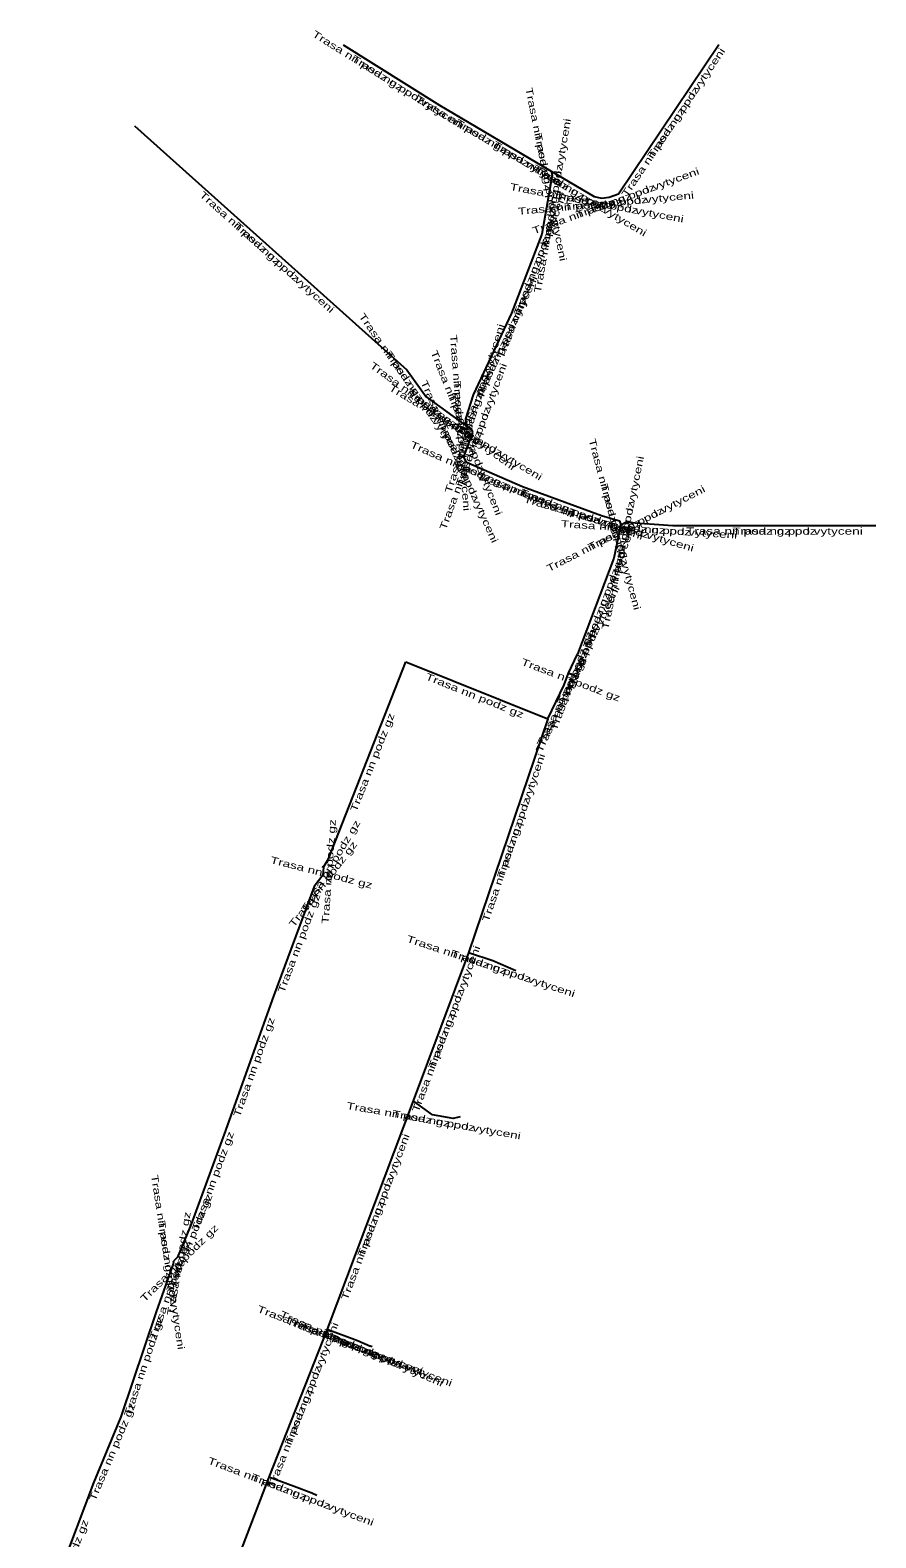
# Model space of a CAD drawing. Extents: x -644332 to -644190, y -1042435 to -1042173.
# Drawn here: x -644249.9 to -644189.5, y -1042280.3 to -1042172.8 of the extents above; entities that cross this region are included whole.
import ezdxf
from ezdxf.enums import TextEntityAlignment as Align

# ---------------------------------------------------------------- set-up
doc = ezdxf.new("R2010")
doc.units = 0
doc.header["$LTSCALE"] = 0.2
doc.layers.add('11', color=7, linetype='Continuous', lineweight=25)
doc.layers.add('33', color=7, linetype='Continuous')

msp = doc.modelspace()

# ---------------------------------------------------------------- linework, layer by layer
at = {"layer": '11'}
for p, q in [((-644227.53, -1042173.85), (-644220.65, -1042178.14)), ((-644227.53, -1042173.85), (-644220.65, -1042178.14)), ((-644207.88, -1042184.48), (-644200.71, -1042173.82)), ((-644207.88, -1042184.48), (-644200.71, -1042173.82)), ((-644220.65, -1042178.14), (-644212.68, -1042182.85)), ((-644220.65, -1042178.14), (-644212.68, -1042182.85)), ((-644242.42, -1042179.63), (-644222.97, -1042197.02)), ((-644242.42, -1042179.63), (-644222.97, -1042197.02)), ((-644212.62, -1042183.15), (-644213.35, -1042187.35)), ((-644212.62, -1042183.15), (-644213.35, -1042187.35)), ((-644212.68, -1042182.85), (-644209.61, -1042184.67)), ((-644212.68, -1042182.85), (-644212.62, -1042183.15)), ((-644212.68, -1042182.85), (-644212.62, -1042183.15)), ((-644212.68, -1042182.85), (-644209.61, -1042184.67)), ((-644208.54, -1042184.72), (-644207.88, -1042184.48)), ((-644208.54, -1042184.72), (-644207.88, -1042184.48)), ((-644209.61, -1042184.67), (-644209.08, -1042184.77)), ((-644209.61, -1042184.67), (-644209.08, -1042184.77)), ((-644209.08, -1042184.77), (-644208.54, -1042184.72)), ((-644209.08, -1042184.77), (-644208.54, -1042184.72)), ((-644213.35, -1042187.35), (-644215.52, -1042192.98)), ((-644213.35, -1042187.35), (-644215.52, -1042192.98)), ((-644215.52, -1042192.98), (-644218.25, -1042198.81)), ((-644215.52, -1042192.98), (-644218.25, -1042198.81)), ((-644222.97, -1042197.02), (-644221.61, -1042198.96)), ((-644222.97, -1042197.02), (-644221.61, -1042198.96)), ((-644221.61, -1042198.96), (-644218.75, -1042201.03)), ((-644218.25, -1042198.81), (-644218.79, -1042200.51)), ((-644218.25, -1042198.81), (-644218.79, -1042200.51)), ((-644218.79, -1042200.51), (-644218.75, -1042201.03)), ((-644218.79, -1042200.51), (-644218.75, -1042201.03)), ((-644218.3, -1042201.49), (-644218.94, -1042203.22)), ((-644218.3, -1042201.49), (-644218.94, -1042203.22)), ((-644218.75, -1042201.03), (-644218.4, -1042201.24)), ((-644218.4, -1042201.24), (-644218.3, -1042201.49)), ((-644218.4, -1042201.24), (-644218.3, -1042201.49)), ((-644218.94, -1042203.22), (-644218.78, -1042203.58)), ((-644218.94, -1042203.22), (-644218.78, -1042203.58)), ((-644218.78, -1042203.58), (-644214.72, -1042205.35)), ((-644218.78, -1042203.58), (-644214.72, -1042205.35)), ((-644214.72, -1042205.35), (-644209.1, -1042207.41)), ((-644214.72, -1042205.35), (-644209.1, -1042207.41)), ((-644209.1, -1042207.41), (-644207.8, -1042207.79)), ((-644209.1, -1042207.41), (-644207.8, -1042207.79)), ((-644207.72, -1042208.09), (-644208.21, -1042210.46)), ((-644207.72, -1042208.09), (-644208.21, -1042210.46)), ((-644207.8, -1042207.79), (-644207.72, -1042208.09)), ((-644207.8, -1042207.79), (-644207.72, -1042208.09)), ((-644207.72, -1042208.09), (-644207.35, -1042207.9)), ((-644207.72, -1042208.09), (-644207.35, -1042207.9)), ((-644207.35, -1042207.9), (-644203.99, -1042208.12)), ((-644207.35, -1042207.9), (-644203.99, -1042208.12)), ((-644203.99, -1042208.12), (-644189.51, -1042208.13)), ((-644203.99, -1042208.12), (-644189.51, -1042208.13)), ((-644208.21, -1042210.46), (-644210.79, -1042217.31)), ((-644208.21, -1042210.46), (-644210.79, -1042217.31)), ((-644211.44, -1042218.65), (-644210.79, -1042217.31)), ((-644211.44, -1042218.65), (-644210.79, -1042217.31)), ((-644228.57, -1042231.9), (-644223.05, -1042217.85)), ((-644223.05, -1042217.85), (-644212.91, -1042221.92)), ((-644211.756, -1042219.496), (-644211.44, -1042218.65)), ((-644211.44, -1042218.65), (-644210.829, -1042218.88)), ((-644212.91, -1042221.92), (-644211.756, -1042219.496)), ((-644212.91, -1042221.92), (-644218.57, -1042238.61)), ((-644212.91, -1042221.92), (-644218.57, -1042238.61)), ((-644228.93, -1042232.5), (-644229.013, -1042232.479)), ((-644228.93, -1042232.5), (-644228.97, -1042233.06)), ((-644228.93, -1042232.5), (-644228.57, -1042231.9)), ((-644229.59, -1042233.87), (-644232.5, -1042241.69)), ((-644228.97, -1042233.06), (-644229.59, -1042233.87)), ((-644218.57, -1042238.61), (-644222.53, -1042249.17)), ((-644218.57, -1042238.61), (-644222.53, -1042249.17)), ((-644232.5, -1042241.69), (-644236.02, -1042251.55)), ((-644222.53, -1042249.17), (-644228.67, -1042265.44)), ((-644222.53, -1042249.17), (-644228.67, -1042265.44)), ((-644236.02, -1042251.55), (-644238.37, -1042257.95)), ((-644238.37, -1042257.95), (-644239.35, -1042260.31)), ((-644239.66, -1042260.79), (-644240.87, -1042264.21)), ((-644239.632, -1042260.62), (-644239.66, -1042260.79)), ((-644239.35, -1042260.31), (-644239.636, -1042260.594)), ((-644239.632, -1042260.62), (-644239.636, -1042260.594)), ((-644239.632, -1042260.62), (-644239.636, -1042260.594)), ((-644240.87, -1042264.21), (-644243.38, -1042271.7)), ((-644228.67, -1042265.44), (-644232.82, -1042276)), ((-644228.67, -1042265.44), (-644232.82, -1042276)), ((-644228.67, -1042265.44), (-644226.51, -1042266.27)), ((-644226.51, -1042266.27), (-644225.58, -1042266.67)), ((-644225.444, -1042266.722), (-644225.58, -1042266.67)), ((-644225.444, -1042266.722), (-644225.58, -1042266.67)), ((-644243.38, -1042271.7), (-644245.35, -1042276.4)), ((-644245.35, -1042276.4), (-644249.86, -1042288.43)), ((-644232.82, -1042276), (-644241.24, -1042297.96)), ((-644232.82, -1042276), (-644241.24, -1042297.96))]:
    msp.add_line(p, q, dxfattribs=at)
for points in [[(-644221.61, -1042198.96), (-644218.75, -1042201.03), (-644218.4, -1042201.24)], [(-644215.2, -1042239.9), (-644216.85, -1042239.18), (-644218.57, -1042238.61)], [(-644215.2, -1042239.9), (-644216.85, -1042239.18), (-644218.57, -1042238.61)], [(-644219.17, -1042250.31), (-644219.67, -1042250.42), (-644221.15, -1042250.16), (-644222.53, -1042249.17)], [(-644219.17, -1042250.31), (-644219.67, -1042250.42), (-644221.15, -1042250.16), (-644222.53, -1042249.17)], [(-644228.67, -1042265.44), (-644226.51, -1042266.27), (-644225.58, -1042266.67)], [(-644229.41, -1042277.31), (-644229.76, -1042277.14), (-644231.03, -1042276.68), (-644232.82, -1042276)], [(-644229.41, -1042277.31), (-644229.76, -1042277.14), (-644231.03, -1042276.68), (-644232.82, -1042276)]]:
    msp.add_lwpolyline(points, dxfattribs=at)

# ---------------------------------------------------------------- texts
at = {"layer": '33'}
for s, rotation, width, p in [('Trasa nn podz gz po vytyceni', 328.055, 1.45, (-644224.4348, -1042176.5458)), ('Trasa nn podz', 328.055, 1.4, (-644224.4348, -1042176.546)), ('Trasa nn podz gz po vytyceni', 56.075, 1.45, (-644203.7563, -1042179.5135)), ('Trasa nn podz gz po vytyceni', 281.31, 1.45, (-644213.287, -1042183.127)), ('Trasa nn podz', 56.075, 1.4, (-644203.7558, -1042179.513)), ('Trasa nn podz gz po vytyceni', 329.418, 1.45, (-644216.9967, -1042181.0537)), ('Trasa nn podz', 329.418, 1.4, (-644216.9967, -1042181.0541)), ('Trasa nn podz gz po vytyceni', 80.14, 1.45, (-644212.345, -1042185.3613)), ('Trasa nn podz', 281.31, 1.4, (-644213.2867, -1042183.1275)), ('Trasa nn podz gz po vytyceni', 329.339, 1.45, (-644211.4775, -1042184.3188)), ('Trasa nn podz gz po vytyceni', 19.983, 1.45, (-644207.9879, -1042185.2111)), ('Trasa nn podz', 329.339, 1.4, (-644211.477, -1042184.3188)), ('Trasa nn podz', 80.14, 1.4, (-644212.345, -1042185.3608)), ('Trasa nn podz gz po vytyceni', 318.201, 1.45, (-644233.1296, -1042188.808)), ('Trasa nn podz gz po vytyceni', 68.922, 1.45, (-644213.8288, -1042190.3989)), ('Trasa nn podz gz po vytyceni', 349.315, 1.45, (-644209.4659, -1042185.3588)), ('Trasa nn podz gz po vytyceni', 5.29, 1.45, (-644208.7505, -1042185.3921)), ('Trasa nn podz', 349.315, 1.4, (-644209.4649, -1042185.3586)), ('Trasa nn podz', 19.983, 1.4, (-644207.9884, -1042185.2115)), ('Trasa nn podz', 5.29, 1.4, (-644208.7495, -1042185.3918)), ('Trasa nn podz', 318.201, 1.4, (-644233.1296, -1042188.808)), ('Trasa nn podz', 68.922, 1.4, (-644213.8291, -1042190.3994)), ('Trasa nn podz gz po vytyceni', 64.908, 1.45, (-644216.2966, -1042196.1715)), ('Trasa nn podz gz po vytyceni', 305.032, 1.45, (-644222.8234, -1042198.363)), ('Trasa nn podz gz po vytyceni', 72.378, 1.45, (-644217.9005, -1042199.8572)), ('Trasa nn podz', 64.908, 1.4, (-644216.2964, -1042196.172)), ('Trasa nn podz gz po vytyceni', 274.399, 1.45, (-644219.4179, -1042200.8208)), ('Trasa nn podz', 305.032, 1.4, (-644222.8238, -1042198.3625)), ('Trasa nn podz gz po vytyceni', 291.801, 1.45, (-644218.9535, -1042201.6067)), ('Trasa nn podz gz po vytyceni', 324.104, 1.45, (-644220.5631, -1042200.5203)), ('Trasa nn podz gz po vytyceni', 69.698, 1.45, (-644218.0105, -1042202.5812)), ('Trasa nn podz', 72.378, 1.4, (-644217.9011, -1042199.8572)), ('Trasa nn podz gz po vytyceni', 329.036, 1.45, (-644218.9106, -1042201.692)), ('Trasa nn podz', 324.104, 1.4, (-644220.5621, -1042200.5208)), ('Trasa nn podz gz po vytyceni', 293.962, 1.45, (-644219.4541, -1042203.6635)), ('Trasa nn podz', 274.399, 1.4, (-644219.4186, -1042200.8203)), ('Trasa nn podz', 291.801, 1.4, (-644218.9531, -1042201.6062)), ('Trasa nn podz', 329.036, 1.4, (-644218.9106, -1042201.692)), ('Trasa nn podz', 69.698, 1.4, (-644218.011, -1042202.5812)), ('Trasa nn podz', 293.962, 1.4, (-644219.4548, -1042203.663)), ('Trasa nn podz gz po vytyceni', 336.445, 1.45, (-644217.0104, -1042205.0612)), ('Trasa nn podz gz po vytyceni', 284.931, 1.45, (-644208.3876, -1042208.1066)), ('Trasa nn podz', 336.445, 1.4, (-644217.0104, -1042205.0606)), ('Trasa nn podz gz po vytyceni', 78.319, 1.45, (-644207.3287, -1042209.4071)), ('Trasa nn podz gz po vytyceni', 339.87, 1.45, (-644212.134, -1042206.9904)), ('Trasa nn podz', 339.87, 1.4, (-644212.134, -1042206.9901)), ('Trasa nn podz gz po vytyceni', 343.706, 1.45, (-644208.6321, -1042208.2239)), ('Trasa nn podz gz po vytyceni', 27.181, 1.45, (-644207.2387, -1042208.5742)), ('Trasa nn podz', 284.931, 1.4, (-644208.388, -1042208.1071)), ('Trasa nn podz', 343.706, 1.4, (-644208.6321, -1042208.224)), ('Trasa nn podz', 27.181, 1.4, (-644207.2387, -1042208.5735)), ('Trasa nn podz', 78.319, 1.4, (-644207.3277, -1042209.4066)), ('Trasa nn podz gz po vytyceni', 356.254, 1.45, (-644205.7118, -1042208.6584)), ('Trasa nn podz gz po vytyceni', 69.362, 1.45, (-644208.8918, -1042214.1141)), ('Trasa nn podz', 356.254, 1.4, (-644205.7118, -1042208.6587)), ('Trasa nn podz gz po vytyceni', 359.96, 1.45, (-644196.7502, -1042208.7747)), ('Trasa nn podz', 359.96, 1.4, (-644196.7502, -1042208.7752)), ('Trasa nn podz', 69.362, 1.4, (-644208.8916, -1042214.1146)), ('Trasa nn podz gz po vytyceni', 64.123, 1.45, (-644210.5303, -1042218.2651)), ('Trasa nn podz', 64.123, 1.4, (-644210.5306, -1042218.2646)), ('Trasa nn podz gz', 69.518, 1.45, (-644210.9888, -1042219.301)), ('Trasa nn podz gz', 339.372, 1.45, (-644211.3636, -1042219.3725)), ('Trasa nn podz gz', 64.542, 1.45, (-644211.7466, -1042220.988)), ('Trasa nn podz gz', 338.13, 1.45, (-644218.2231, -1042220.4881)), ('Trasa nn podz gz', 68.551, 1.45, (-644225.2054, -1042225.1124)), ('Trasa nn podz gz po vytyceni', 71.267, 1.45, (-644215.1248, -1042230.4738)), ('Trasa nn podz', 71.267, 1.4, (-644215.1242, -1042230.4733)), ('Trasa nn podz gz', 59.036, 1.45, (-644228.1933, -1042232.5351)), ('Trasa nn podz gz', 85.914, 1.45, (-644228.3016, -1042232.8263)), ('Trasa nn podz gz', 52.568, 1.45, (-644228.764, -1042233.861)), ('Trasa nn podz gz', 345.801, 1.45, (-644229.1313, -1042233.119)), ('Trasa nn podz gz', 69.589, 1.45, (-644230.4362, -1042238.0072)), ('Trasa nn podz gz po vytyceni', 341.665, 1.45, (-644217.0596, -1042239.7952)), ('Trasa nn podz gz po vytyceni', 69.444, 1.45, (-644219.941, -1042244.1178)), ('Trasa nn podz', 341.665, 1.4, (-644217.0596, -1042239.795)), ('Trasa nn podz', 69.444, 1.4, (-644219.941, -1042244.1183)), ('Trasa nn podz gz', 70.354, 1.45, (-644233.6481, -1042246.8386)), ('Trasa nn podz gz po vytyceni', 350.036, 1.45, (-644221.1063, -1042250.8273)), ('Trasa nn podz', 350.036, 1.4, (-644221.1058, -1042250.8276)), ('Trasa nn podz gz', 69.837, 1.45, (-644236.585, -1042254.9742)), ('Trasa nn podz gz po vytyceni', 69.324, 1.45, (-644224.9927, -1042257.5348)), ('Trasa nn podz gz po vytyceni', 278.746, 1.45, (-644240.2761, -1042260.706)), ('Trasa nn podz', 69.324, 1.4, (-644224.9919, -1042257.5348)), ('Trasa nn podz gz', 67.449, 1.45, (-644238.2599, -1042259.3794)), ('Trasa nn podz gz', 80.647, 1.45, (-644239.0042, -1042260.8111)), ('Trasa nn podz gz', 44.799, 1.45, (-644239.0362, -1042260.9145)), ('Trasa nn podz', 278.746, 1.4, (-644240.2764, -1042260.706)), ('Trasa nn podz gz', 70.516, 1.45, (-644239.6525, -1042262.7169)), ('Trasa nn podz gz po vytyceni', 338.98, 1.45, (-644227.8237, -1042266.4615)), ('Trasa nn podz gz', 71.473, 1.45, (-644241.5089, -1042268.1614)), ('Trasa nn podz gz po vytyceni', 68.546, 1.45, (-644230.1401, -1042270.9584)), ('Trasa nn podz gz po vytyceni', 336.727, 1.45, (-644226.3028, -1042267.0665)), ('Trasa nn podz gz po vytyceni', 339.075, 1.45, (-644225.7443, -1042267.3031)), ('Trasa nn podz', 338.98, 1.4, (-644227.8232, -1042266.4609)), ('Trasa nn podz', 336.727, 1.4, (-644226.3018, -1042267.0665)), ('Trasa nn podz', 339.075, 1.4, (-644225.7443, -1042267.303)), ('Trasa nn podz', 68.546, 1.4, (-644230.1409, -1042270.9579)), ('Trasa nn podz gz', 67.259, 1.45, (-644243.7661, -1042274.3026)), ('Trasa nn podz gz po vytyceni', 339.199, 1.45, (-644231.3433, -1042277.2562)), ('Trasa nn podz', 339.199, 1.4, (-644231.3428, -1042277.2567)), ('Trasa nn podz gz', 69.449, 1.45, (-644246.9964, -1042282.6438))]:
    msp.add_text(s, height=0.5, rotation=rotation, dxfattribs=dict(at, width=width)).set_placement(p, align=Align.CENTER)

doc.saveas('drawing.dxf')
